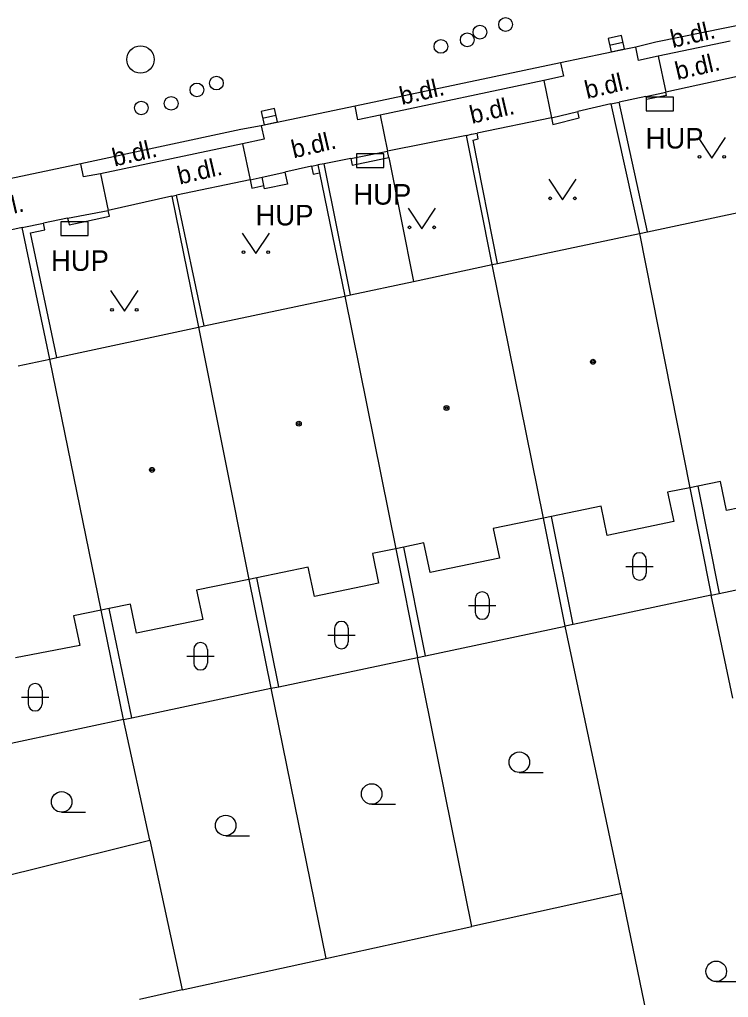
# Model space of a CAD drawing. Extents: x -596229 to -595156, y -1161237 to -1159376.
# Drawn here: x -595887.66 to -595861.78, y -1161054.1 to -1161018.38 of the extents above; entities that cross this region are included whole.
import ezdxf

# ---------------------------------------------------------------- set-up
doc = ezdxf.new("R2010")
doc.units = 0
for name, color, linetype in [('DOP - kresba z DSPS bez souradnic', 7, 'Continuous'), ('DOP - rozhrani ploch obecne', 7, 'Continuous'), ('Level 24', 7, 'Continuous'), ('Level 27', 7, 'Continuous'), ('Level 28', 7, 'Continuous'), ('Level 36', 7, 'Continuous'), ('Level 39', 7, 'Continuous'), ('plynovod - povrch.  znaky - PRIS skut. velikost', 7, 'Continuous'), ('TM - budovy zdene_ betonove - VP', 7, 'Continuous'), ('TM - komunikace - VP', 7, 'Continuous'), ('TM - letecke snimky - pomocna linie', 7, 'Continuous'), ('TM - plot drateny_ kovovy - VP', 7, 'Continuous'), ('TM - podezdivka plotu - VP', 7, 'Continuous'), ('TM - popis objektu', 7, 'Continuous'), ('TM - popis povrchu', 7, 'Continuous'), ('TM - rozhrani ploch obecne - VP', 7, 'Continuous'), ('TM - vjezd na pozemek', 7, 'Continuous')]:
    doc.layers.add(name, color=color, linetype=linetype)

msp = doc.modelspace()

# ---------------------------------------------------------------- linework, layer by layer
at = {"layer": 'DOP - kresba z DSPS bez souradnic'}
for points in [[(-595862.9, -1161035.42), (-595862.12, -1161039.35)], [(-595867.45, -1161040.48), (-595868.24, -1161036.53)], [(-595872.84, -1161041.62), (-595873.64, -1161037.65)], [(-595862.12, -1161039.35), (-595856.9, -1161038.24)], [(-595878.2, -1161042.75), (-595879, -1161038.77)], [(-595862.41, -1161039.41), (-595862.12, -1161039.35)], [(-595883.57, -1161043.89), (-595884.39, -1161039.89)], [(-595883.87, -1161043.95), (-595888.9, -1161045.02)]]:
    msp.add_lwpolyline(points, dxfattribs=at)
at = {"layer": 'DOP - rozhrani ploch obecne'}
for points in [[(-595863.19, -1161035.48), (-595862.41, -1161039.41)], [(-595867.74, -1161040.54), (-595868.54, -1161036.59)], [(-595873.93, -1161037.71), (-595873.14, -1161041.68)], [(-595879.29, -1161038.83), (-595878.49, -1161042.81)], [(-595862.41, -1161039.41), (-595867.45, -1161040.48)], [(-595861.62, -1161043.17), (-595862.41, -1161039.41)], [(-595883.87, -1161043.95), (-595884.68, -1161039.95)], [(-595867.45, -1161040.48), (-595867.74, -1161040.54)], [(-595872.84, -1161041.62), (-595867.74, -1161040.54)], [(-595865.68, -1161050.3), (-595867.74, -1161040.54)], [(-595878.2, -1161042.75), (-595873.14, -1161041.68)], [(-595873.14, -1161041.68), (-595872.84, -1161041.62)], [(-595871.15, -1161051.51), (-595873.14, -1161041.68)], [(-595883.57, -1161043.89), (-595878.49, -1161042.81)], [(-595878.49, -1161042.81), (-595878.2, -1161042.75)], [(-595878.49, -1161042.81), (-595876.48, -1161052.68)], [(-595883.87, -1161043.95), (-595883.57, -1161043.89)], [(-595882.91, -1161048.36), (-595883.87, -1161043.95)], [(-595888.22, -1161049.67), (-595882.91, -1161048.36)], [(-595882.91, -1161048.36), (-595881.73, -1161053.83)], [(-595865.68, -1161050.3), (-595871.15, -1161051.51)], [(-595864.52, -1161055.92), (-595865.68, -1161050.3)], [(-595876.48, -1161052.68), (-595871.15, -1161051.51)], [(-595881.73, -1161053.83), (-595876.48, -1161052.68)], [(-595881.73, -1161053.83), (-595883.29, -1161054.18)]]:
    msp.add_lwpolyline(points, dxfattribs=at)
at = {"layer": 'Level 24'}
for points in [[(-595864.788, -1161021.709), (-595863.788, -1161021.709), (-595863.788, -1161021.209), (-595864.788, -1161021.209)], [(-595875.368, -1161023.789), (-595874.368, -1161023.789), (-595874.368, -1161023.289), (-595875.368, -1161023.289)], [(-595886.158, -1161026.269), (-595885.158, -1161026.269), (-595885.158, -1161025.769), (-595886.158, -1161025.769)]]:
    msp.add_lwpolyline(points, close=True, dxfattribs=at)
at = {"layer": 'Level 27'}
for p, q in [((-595866.124, -1161019.316), (-595865.636, -1161019.204)), ((-595878.794, -1161021.986), (-595878.306, -1161021.874))]:
    msp.add_line(p, q, dxfattribs=at)
for points in [[(-595866.067, -1161019.56), (-595865.58, -1161019.447), (-595865.693, -1161018.96), (-595866.18, -1161019.073)], [(-595878.737, -1161022.23), (-595878.25, -1161022.117), (-595878.363, -1161021.63), (-595878.85, -1161021.743)]]:
    msp.add_lwpolyline(points, close=True, dxfattribs=at)
msp.add_circle((-595883.25, -1161019.84), 0.5, dxfattribs=at)
at = {"layer": 'Level 28'}
for centre in [(-595869.92, -1161018.56), (-595870.86, -1161018.84), (-595871.32, -1161019.12), (-595872.28, -1161019.36), (-595880.48, -1161020.7), (-595881.19, -1161020.95), (-595882.13, -1161021.44), (-595883.22, -1161021.61)]:
    msp.add_circle(centre, 0.25, dxfattribs=at)
at = {"layer": 'Level 36'}
for p, q in [((-595865.536, -1161038.356), (-595864.536, -1161038.356)), ((-595865.286, -1161038.106), (-595865.286, -1161038.606)), ((-595864.786, -1161038.106), (-595864.786, -1161038.606)), ((-595871.276, -1161039.786), (-595870.276, -1161039.786)), ((-595871.026, -1161039.536), (-595871.026, -1161040.036)), ((-595870.526, -1161039.536), (-595870.526, -1161040.036)), ((-595876.416, -1161040.866), (-595875.416, -1161040.866)), ((-595876.166, -1161040.616), (-595876.166, -1161041.116)), ((-595875.666, -1161040.616), (-595875.666, -1161041.116)), ((-595881.306, -1161041.386), (-595881.306, -1161041.886)), ((-595880.806, -1161041.386), (-595880.806, -1161041.886)), ((-595881.556, -1161041.636), (-595880.556, -1161041.636)), ((-595887.346, -1161042.886), (-595887.346, -1161043.386)), ((-595886.846, -1161042.886), (-595886.846, -1161043.386)), ((-595887.596, -1161043.136), (-595886.596, -1161043.136)), ((-595869.42, -1161045.885), (-595868.545, -1161045.885)), ((-595874.81, -1161047.045), (-595873.935, -1161047.045)), ((-595886.13, -1161047.335), (-595885.255, -1161047.335)), ((-595880.14, -1161048.195), (-595879.265, -1161048.195)), ((-595862.23, -1161053.525), (-595861.355, -1161053.525))]:
    msp.add_line(p, q, dxfattribs=at)
for points in [[(-595862.89, -1161022.69), (-595862.39, -1161023.44), (-595861.89, -1161022.69)], [(-595868.34, -1161024.21), (-595867.84, -1161024.96), (-595867.34, -1161024.21)], [(-595873.48, -1161025.27), (-595872.98, -1161026.02), (-595872.48, -1161025.27)], [(-595879.54, -1161026.18), (-595879.04, -1161026.93), (-595878.54, -1161026.18)], [(-595884.34, -1161028.28), (-595883.84, -1161029.03), (-595883.34, -1161028.28)]]:
    msp.add_lwpolyline(points, dxfattribs=at)
for centre, radius in [((-595862.84, -1161023.39), 0.05), ((-595861.941, -1161023.39), 0.05), ((-595868.29, -1161024.91), 0.05), ((-595867.391, -1161024.91), 0.05), ((-595873.43, -1161025.97), 0.05), ((-595872.531, -1161025.97), 0.05), ((-595879.49, -1161026.88), 0.05), ((-595878.591, -1161026.88), 0.05), ((-595884.29, -1161028.98), 0.05), ((-595883.391, -1161028.98), 0.05), ((-595869.42, -1161045.51), 0.375), ((-595874.81, -1161046.67), 0.375), ((-595886.13, -1161046.96), 0.375), ((-595880.14, -1161047.82), 0.375), ((-595862.23, -1161053.15), 0.375)]:
    msp.add_circle(centre, radius, dxfattribs=at)
for centre, start, end in [((-595865.036, -1161038.106), 0, 180), ((-595865.036, -1161038.606), 180, 0), ((-595870.776, -1161039.536), 0, 180), ((-595870.776, -1161040.036), 180, 0), ((-595875.916, -1161040.616), 0, 180), ((-595881.056, -1161041.386), 0, 180), ((-595875.916, -1161041.116), 180, 0), ((-595881.056, -1161041.886), 180, 0), ((-595887.096, -1161042.886), 0, 180), ((-595887.096, -1161043.386), 180, 0)]:
    msp.add_arc(centre, 0.25, start, end, dxfattribs=at)
at = {"layer": 'Level 39'}
for centre, radius in [((-595866.73, -1161030.88), 0.09), ((-595866.73, -1161030.88), 0.0398), ((-595872.08, -1161032.57), 0.09), ((-595872.08, -1161032.57), 0.0398), ((-595877.47, -1161033.14), 0.09), ((-595877.47, -1161033.14), 0.0398), ((-595882.83, -1161034.83), 0.09), ((-595882.83, -1161034.83), 0.0398)]:
    msp.add_circle(centre, radius, dxfattribs=at)
at = {"layer": 'plynovod - povrch.  znaky - PRIS skut. velikost'}
for points in [[(-595877.98, -1161023.96), (-595877.88, -1161024.39)], [(-595878.75, -1161024.44), (-595878.81, -1161024.14)], [(-595877.88, -1161024.39), (-595878.72, -1161024.56), (-595878.75, -1161024.44)]]:
    msp.add_lwpolyline(points, dxfattribs=at)
at = {"layer": 'TM - budovy zdene_ betonove - VP'}
for points in [[(-595864.74, -1161026.13), (-595859.78, -1161025.07)], [(-595870.22, -1161027.29), (-595865.03, -1161026.19)], [(-595865.03, -1161026.19), (-595864.74, -1161026.13)], [(-595865.03, -1161026.19), (-595863.19, -1161035.48)], [(-595870.41, -1161027.33), (-595870.22, -1161027.29)], [(-595873.28, -1161027.95), (-595870.41, -1161027.33)], [(-595868.54, -1161036.59), (-595870.41, -1161027.33)], [(-595875.58, -1161028.44), (-595873.28, -1161027.95)], [(-595880.92, -1161029.57), (-595875.79, -1161028.48)], [(-595875.79, -1161028.48), (-595875.58, -1161028.44)], [(-595875.79, -1161028.48), (-595873.93, -1161037.71)], [(-595886.31, -1161030.73), (-595881.13, -1161029.62)], [(-595881.13, -1161029.62), (-595880.92, -1161029.57)], [(-595881.13, -1161029.62), (-595879.29, -1161038.83)], [(-595887.72, -1161031.03), (-595886.56, -1161030.78)], [(-595886.56, -1161030.78), (-595886.31, -1161030.73)], [(-595884.68, -1161039.95), (-595886.56, -1161030.78)], [(-595863.19, -1161035.48), (-595864.01, -1161035.65)], [(-595862.9, -1161035.42), (-595863.19, -1161035.48)], [(-595862.08, -1161035.25), (-595862.9, -1161035.42)], [(-595861.85, -1161036.32), (-595862.08, -1161035.25)], [(-595864.01, -1161035.65), (-595863.78, -1161036.72)], [(-595859.48, -1161035.83), (-595861.85, -1161036.32)], [(-595866.43, -1161036.15), (-595868.24, -1161036.53)], [(-595866.21, -1161037.23), (-595866.43, -1161036.15)], [(-595868.24, -1161036.53), (-595868.54, -1161036.59)], [(-595868.54, -1161036.59), (-595870.37, -1161036.97)], [(-595863.78, -1161036.72), (-595866.21, -1161037.23)], [(-595870.37, -1161036.97), (-595870.14, -1161038.05)], [(-595873.64, -1161037.65), (-595873.93, -1161037.71)], [(-595872.9, -1161037.5), (-595873.64, -1161037.65)], [(-595872.68, -1161038.58), (-595872.9, -1161037.5)], [(-595873.93, -1161037.71), (-595874.78, -1161037.89)], [(-595874.78, -1161037.89), (-595874.56, -1161038.97)], [(-595870.14, -1161038.05), (-595872.68, -1161038.58)], [(-595877.13, -1161038.38), (-595879, -1161038.77)], [(-595876.9, -1161039.45), (-595877.13, -1161038.38)], [(-595879.29, -1161038.83), (-595881.2, -1161039.22)], [(-595879, -1161038.77), (-595879.29, -1161038.83)], [(-595874.56, -1161038.97), (-595876.9, -1161039.45)], [(-595881.2, -1161039.22), (-595880.98, -1161040.3)], [(-595883.62, -1161039.73), (-595884.39, -1161039.89)], [(-595883.4, -1161040.8), (-595883.62, -1161039.73)], [(-595884.68, -1161039.95), (-595885.7, -1161040.16)], [(-595884.39, -1161039.89), (-595884.68, -1161039.95)], [(-595885.7, -1161040.16), (-595885.47, -1161041.24)], [(-595880.98, -1161040.3), (-595883.4, -1161040.8)], [(-595885.47, -1161041.24), (-595887.81, -1161041.7)]]:
    msp.add_lwpolyline(points, dxfattribs=at)
at = {"layer": 'TM - komunikace - VP'}
for points in [[(-595861.08, -1161018.52), (-595861.86, -1161018.68), (-595864.44, -1161019.21), (-595865.17, -1161019.39)], [(-595865.17, -1161019.39), (-595865.47, -1161019.45), (-595867.91, -1161019.96)], [(-595867.91, -1161019.96), (-595875.41, -1161021.54)], [(-595875.41, -1161021.54), (-595878.85, -1161022.26)], [(-595878.85, -1161022.26), (-595879.59, -1161022.4), (-595885.43, -1161023.65)], [(-595885.43, -1161023.65), (-595892.64, -1161025.17)]]:
    msp.add_lwpolyline(points, dxfattribs=at)
at = {"layer": 'TM - letecke snimky - pomocna linie'}
msp.add_lwpolyline([(-595874.18, -1161023.42), (-595873.28, -1161027.95)], dxfattribs=at)
at = {"layer": 'TM - plot drateny_ kovovy - VP'}
for points in [[(-595864.74, -1161026.13), (-595865.78, -1161021.4)], [(-595867.23, -1161021.97), (-595867.28, -1161021.74)], [(-595868.24, -1161021.97), (-595868.2, -1161022.21), (-595867.23, -1161021.97)], [(-595870.22, -1161027.29), (-595871.11, -1161022.78), (-595870.92, -1161022.74), (-595870.96, -1161022.53)], [(-595875.58, -1161028.44), (-595876.55, -1161023.65)], [(-595875.52, -1161023.7), (-595875.35, -1161023.66)], [(-595875.35, -1161023.66), (-595874.18, -1161023.42)], [(-595876.95, -1161024.03), (-595876.71, -1161023.98)], [(-595879.25, -1161024.24), (-595879.19, -1161024.54), (-595878.75, -1161024.44)], [(-595880.92, -1161029.57), (-595881.94, -1161024.8)], [(-595885.86, -1161025.88), (-595885.22, -1161025.74), (-595884.38, -1161025.56)], [(-595886.31, -1161030.73), (-595887.26, -1161026.17), (-595886.74, -1161026.06)]]:
    msp.add_lwpolyline(points, dxfattribs=at)
at = {"layer": 'TM - podezdivka plotu - VP'}
for points in [[(-595864.8, -1161021.19), (-595864.07, -1161021.03)], [(-595864.8, -1161021.19), (-595864.78, -1161021.3)], [(-595864.05, -1161021.15), (-595864.78, -1161021.3)], [(-595864.05, -1161021.15), (-595864.07, -1161021.03)], [(-595866.08, -1161021.46), (-595865.78, -1161021.4)], [(-595866.08, -1161021.46), (-595865.03, -1161026.19)], [(-595868.24, -1161021.97), (-595867.28, -1161021.74)], [(-595871.35, -1161022.61), (-595871.16, -1161022.57)], [(-595870.41, -1161027.33), (-595871.35, -1161022.61)], [(-595871.16, -1161022.57), (-595870.96, -1161022.53)], [(-595875.57, -1161023.45), (-595874.23, -1161023.19)], [(-595874.18, -1161023.42), (-595874.23, -1161023.19)], [(-595877.01, -1161023.74), (-595876.78, -1161023.69)], [(-595876.55, -1161023.65), (-595876.78, -1161023.69)], [(-595876.78, -1161023.69), (-595876.71, -1161023.98)], [(-595875.57, -1161023.45), (-595875.52, -1161023.7)], [(-595878.81, -1161024.14), (-595877.98, -1161023.96)], [(-595877.01, -1161023.74), (-595876.95, -1161024.03)], [(-595876.71, -1161023.98), (-595875.79, -1161028.48)], [(-595879.25, -1161024.24), (-595878.81, -1161024.14)], [(-595882.11, -1161024.83), (-595881.94, -1161024.8)], [(-595882.11, -1161024.83), (-595881.13, -1161029.62)], [(-595885.91, -1161025.63), (-595884.43, -1161025.36)], [(-595884.38, -1161025.56), (-595884.43, -1161025.36)], [(-595887.57, -1161025.97), (-595886.79, -1161025.82)], [(-595886.74, -1161026.06), (-595886.79, -1161025.82)], [(-595885.91, -1161025.63), (-595885.87, -1161025.81), (-595885.86, -1161025.88)], [(-595886.56, -1161030.78), (-595887.57, -1161025.97)]]:
    msp.add_lwpolyline(points, dxfattribs=at)
at = {"layer": 'TM - rozhrani ploch obecne - VP'}
for points in [[(-595864.35, -1161019.72), (-595865.07, -1161019.87), (-595865.17, -1161019.39)], [(-595861.72, -1161019.17), (-595864.35, -1161019.72)], [(-595864.35, -1161019.72), (-595864.07, -1161021.03)], [(-595867.91, -1161019.96), (-595867.81, -1161020.45), (-595868.52, -1161020.61)], [(-595868.52, -1161020.61), (-595874.5, -1161021.87)], [(-595868.52, -1161020.61), (-595868.24, -1161021.97)], [(-595874.5, -1161021.87), (-595875.31, -1161022.04), (-595875.41, -1161021.54)], [(-595874.5, -1161021.87), (-595874.23, -1161023.19)], [(-595878.85, -1161022.26), (-595878.74, -1161022.75), (-595879.53, -1161022.92)], [(-595879.53, -1161022.92), (-595884.71, -1161024.01)], [(-595879.53, -1161022.92), (-595879.25, -1161024.24)], [(-595884.71, -1161024.01), (-595885.33, -1161024.13), (-595885.43, -1161023.65)], [(-595884.71, -1161024.01), (-595884.43, -1161025.36)]]:
    msp.add_lwpolyline(points, dxfattribs=at)
at = {"layer": 'TM - vjezd na pozemek'}
for points in [[(-595861.45, -1161020.46), (-595864.07, -1161021.03)], [(-595864.8, -1161021.19), (-595865.78, -1161021.4)], [(-595866.08, -1161021.46), (-595867.28, -1161021.74)], [(-595868.24, -1161021.97), (-595870.96, -1161022.53)], [(-595871.35, -1161022.61), (-595874.23, -1161023.19)], [(-595875.57, -1161023.45), (-595876.55, -1161023.65)], [(-595877.01, -1161023.74), (-595877.98, -1161023.96)], [(-595879.25, -1161024.24), (-595881.94, -1161024.8)], [(-595882.11, -1161024.83), (-595884.43, -1161025.36)], [(-595885.91, -1161025.63), (-595886.79, -1161025.82)], [(-595887.57, -1161025.97), (-595888.73, -1161026.23)]]:
    msp.add_lwpolyline(points, dxfattribs=at)

# ---------------------------------------------------------------- texts
at = {"layer": 'TM - popis objektu'}
for p in [(-595864.81, -1161023.09), (-595875.48, -1161025.14), (-595879.05, -1161025.9), (-595886.52, -1161027.56)]:
    msp.add_text('HUP', height=0.75, dxfattribs=at).set_placement(p)
at = {"layer": 'TM - popis povrchu'}
for p in [(-595863.82, -1161019.42), (-595863.65, -1161020.59), (-595866.95, -1161021.28), (-595873.71, -1161021.5), (-595871.15, -1161022.19), (-595877.66, -1161023.45), (-595884.2, -1161023.75), (-595881.82, -1161024.41), (-595889.06, -1161025.75)]:
    msp.add_text('b.dl.', height=0.65, rotation=13.11, dxfattribs=at).set_placement(p)

doc.saveas('drawing.dxf')
